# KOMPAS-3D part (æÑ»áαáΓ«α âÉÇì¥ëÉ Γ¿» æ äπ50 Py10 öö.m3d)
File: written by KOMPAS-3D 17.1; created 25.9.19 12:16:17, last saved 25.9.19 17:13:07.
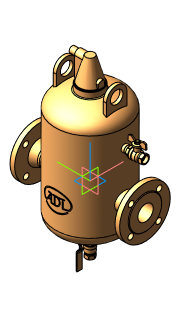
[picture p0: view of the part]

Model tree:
1. Операция без истории:4  (with: Сечение модели:1)  (labels: Сталь 20  ГОСТ 1050-2013)

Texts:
  Точка начала. Х
  Точка начала. Y
  Точка начала. Z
